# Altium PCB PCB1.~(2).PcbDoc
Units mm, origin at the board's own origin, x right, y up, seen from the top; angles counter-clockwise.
Board outline 50.2 x 30 mm, 2 copper layers (Top Layer, Bottom Layer); 14 components, 11 nets, 35 pads, 0 vias.
Unrouted connection lines stored in the file: 24.
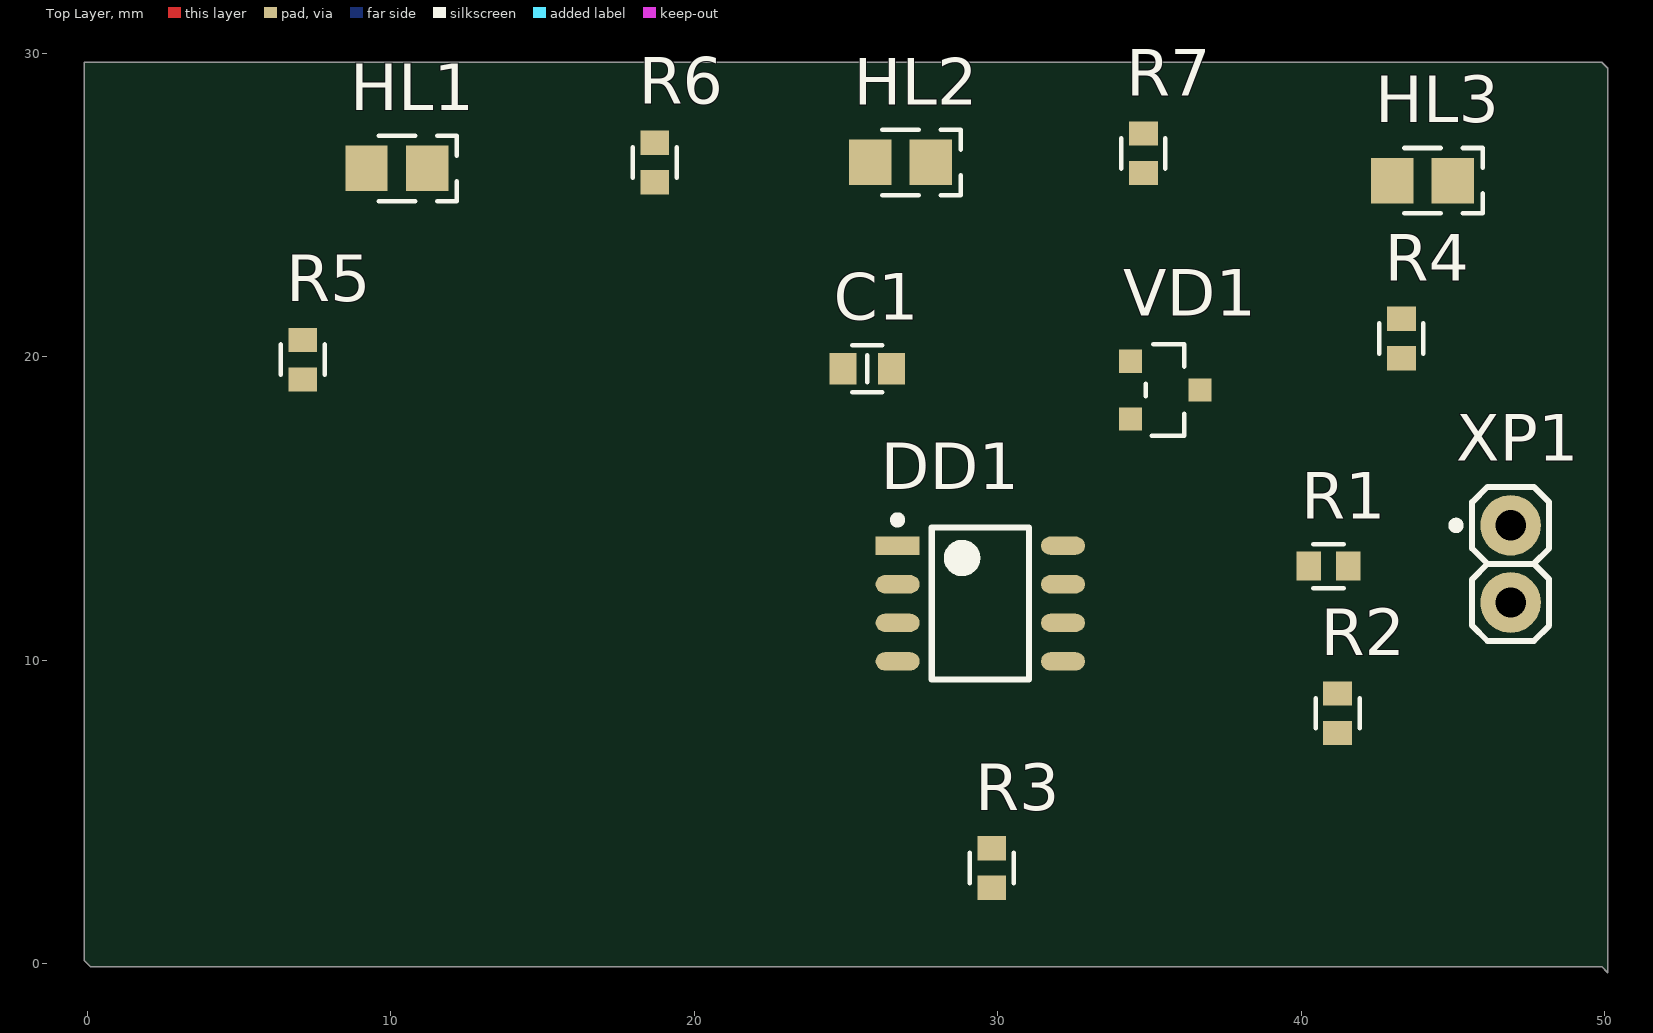
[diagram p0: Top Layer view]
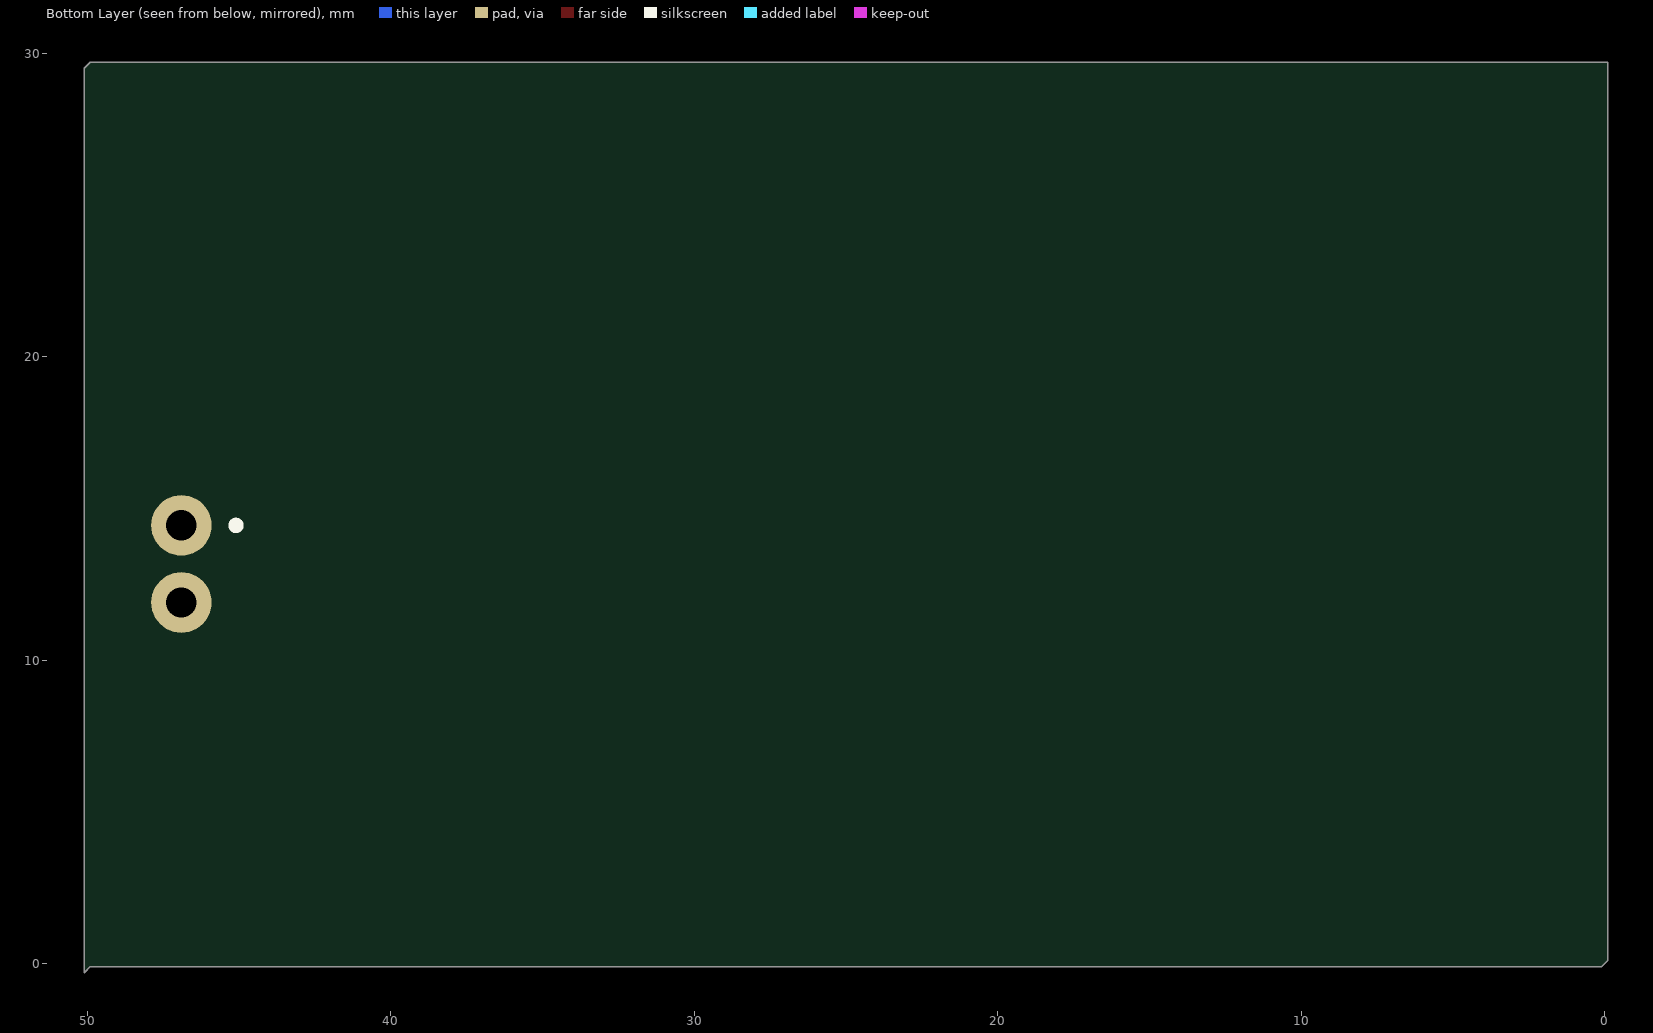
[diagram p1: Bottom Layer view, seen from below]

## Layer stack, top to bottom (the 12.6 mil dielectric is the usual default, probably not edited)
Top Solder: solder mask 0.0102, Solder Resist, Dk 3.5
Top Layer: signal copper 0.0356
Dielectric 1: dielectric 0.32, FR-4, Dk 4.8
Bottom Layer: signal copper 0.0356
Bottom Solder: solder mask 0.0102, Solder Resist, Dk 3.5

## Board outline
0.1,-0.1 -0.1,0.1 -0.1,29.7 49.9,29.7 50.1,29.5 50.1,-0.3 49.9,-0.1

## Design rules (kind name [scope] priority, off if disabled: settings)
Clearance [All] p1: gap=0.254 ignorepadtopadclearanceinfootprint=FALSE
PolygonConnect [All] p1: connectstyle=Relief reliefconductorwidth=0.254 reliefentries=4 polygonreliefangle="90 Angle" airgapwidth=0.254
RoutingVias [All] p1: holewidth=0.711 width=1.27 viastyle="Through Hole" minholewidth=0.711 minwidth=1.27 maxholewidth=0.711 maxwidth=1.27
SolderMaskExpansion [All] p1: expansion=0.102 istentingtop=FALSE
Width [All] p1: maxlimit=0.254 minlimit=0.254 preferedwidth=0.254
30 further rules are at their usual default settings.

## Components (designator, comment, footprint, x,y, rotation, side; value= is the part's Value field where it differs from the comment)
C1 "Capacitor" 0603C 25.7,19.6 r0 top value="0,1 мк"
DD1 "LM393" SOIC-8 29.425,11.865 r0 top
HL1 "LED" 0805D 10.2,26.2 r0 top
HL2 "LED" 0805D 26.8,26.4 r0 top
HL3 "LED" 0805D 44,25.8 r0 top
R1 "Resistor" 0603R 40.9,13.1 r0 top value=10
R2 "Resistor" 0603R 41.2,8.25 r90 top value=4,3
R3 "Resistor" 0603R 29.8,3.15 r90 top value="43 к"
R4 "Resistor" 0603R 43.3,20.6 r90 top value=4,3
R5 "Resistor" 0603R 7.1,19.9 r90 top value="10 к"
R6 "Resistor" 0603R 18.7,26.4 r90 top value="10 к"
R7 "Resistor" 0603R 34.8,26.7 r90 top value="10 к"
VD1 "BZX84-B11" SOT23-3 35.5,18.9 r0 top value="11 В"
XP1 "PLS-2" PLS2 46.9,14.44 r0 top

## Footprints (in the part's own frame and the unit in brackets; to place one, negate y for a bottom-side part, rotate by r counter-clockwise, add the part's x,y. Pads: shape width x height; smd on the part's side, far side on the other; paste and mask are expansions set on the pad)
0603C [mm] "Chip Resistor, 2-Leads, Body 1,40x0,80mm, IPC Medium Density"
  rect 0.9x1.05 smd: 1(-0.8,0) 2(0.8,0)
  silkscreen extent -0.5,-0.77 0.5,0.77, body extent -0.85,-0.45 0.85,0.45, height 0.9
0603R [mm] "Chip Resistor, 2-Leads, Body 1.60x0.85mm, IPC Medium Density"
  rect 0.8x0.95 smd: 1(-0.65,0) 2(0.65,0)
  silkscreen extent -0.5,-0.72 0.5,0.72, body extent -0.87,-0.47 0.88,0.48, height 0.9
0805D [mm]
  rect 1.4x1.5 smd: 1(-1,0) 2(1,0)
  silkscreen extent -0.6,-1.07 1.97,1.07, body extent -1.07,-0.7 1.07,0.7, height 0.7
PLS2 [mm]
  round 2 hole 1: 1(0,0) 2(0,-2.54)
  silkscreen extent -1.92,-3.81 1.27,1.27, body extent -1.27,-3.81 1.27,1.27, height 8.44
SOIC-8 [mm] "for operational amplifier"
  rect 1.45x0.6 smd: 1(-2.725,1.905)
  oval 1.45x0.6 smd: 2(-2.725,0.635) 3(-2.725,-0.635) 4(-2.725,-1.905) 5(2.725,-1.905) 6(2.725,-0.635) 7(2.725,0.635) 8(2.725,1.905)
  silkscreen extent -2.85,-2.5 1.6,2.88, body extent -3,-2.5 3,2.5, height 1.75
SOT23-3 [mil]
  rect 30x30 smd: 1(-44.29,37.4) 2(-44.29,-37.6) 3(45.71,-0.1)
  silkscreen extent -25,-59 26,59, body extent -48,-60 50,59, height 41

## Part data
C1: library part Capacitor_0,1u_10_50V_X7R_0603C, "Конденсатор 0603C ёмкостью 0,1 мк 10%, 50 В, X7R", Capacity (nF)=100, Dielectric=X7R, Tolerance=10%, Voltage (V)=50
DD1: "Двойной маломощный компаратор напряжения", Package="SOIC-8 Texas Instruments"
HL1: "Светодиод", Color=Красный
HL2: "Светодиод", Color=Желтый
HL3: "Светодиод", Color=Зеленый
R1: library part Resistor_10_1_0603, "Резистор номиналом 10 Ом 1%", Tolerance=1%
R2 R4: library part Resistor_4.3_1_0603, "Резистор номиналом 4,3 Ом 1%", Tolerance=1%
R3: library part Resistor_43k_1_0603, "Резистор номиналом 43 кОм 1%", Tolerance=1%
R5 R6 R7: library part Resistor_10k_1_0603, "Резистор номиналом 10 кОм 1%", Tolerance=1%
VD1: "Стабилитрон на 11 В, рассеиваемая мощность 0.25 Вт", Current nominal (mA)=5, Power (W)=0.25, Voltage nominal (V)=11
XP1: "Гребенка 2 пина"

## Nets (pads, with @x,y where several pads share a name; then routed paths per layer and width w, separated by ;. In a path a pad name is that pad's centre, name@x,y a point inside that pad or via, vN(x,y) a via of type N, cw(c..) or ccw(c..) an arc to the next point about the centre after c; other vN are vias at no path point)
GND: C1.1 DD1.4 HL3.2 R3.1 VD1.1 VD1.2 XP1.2
NetC1_2: C1.2 DD1.8
NetDD1_1: DD1.1 HL1.2 R6.2
NetDD1_2: DD1.2 DD1.6 R4.1 VD1.3
NetDD1_3: DD1.3 R1.1 R2.2
NetDD1_5: DD1.5 R2.1 R3.2
NetDD1_7: DD1.7 HL2.2 R7.2
NetHL1_1: HL1.1 R5.1
NetHL2_1: HL2.1 R6.1
NetHL3_1: HL3.1 R7.1
NetR1_2: R1.2 R4.2 R5.2 XP1.1

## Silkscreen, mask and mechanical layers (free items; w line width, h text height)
Mechanical 1:
  the board outline again, w0.254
